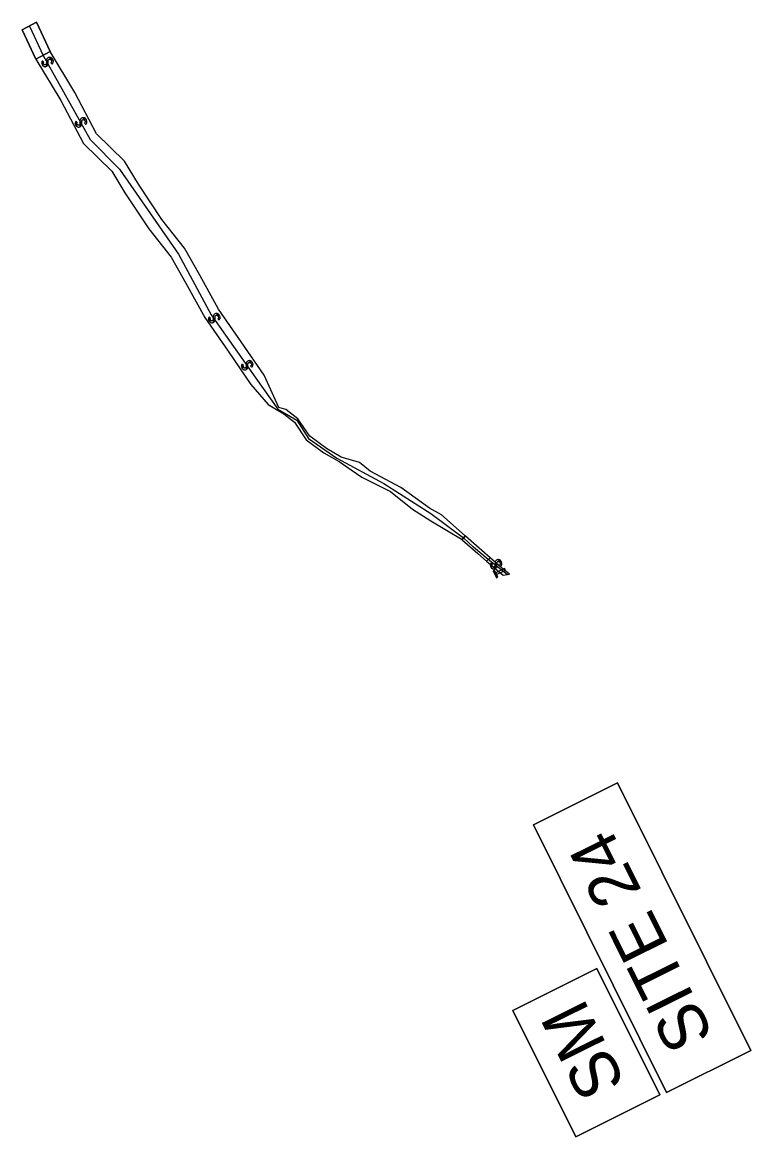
# Model space of a CAD drawing. Extents: x 474218 to 481634, y 484357 to 504997.
# Drawn here: x 475815 to 476040.6, y 502013 to 502358.5 of the extents above; entities that cross this region are included whole.
import ezdxf

# ---------------------------------------------------------------- set-up
doc = ezdxf.new("R2010")
doc.units = 0
for name, color, linetype in [('Exist Hydro Jurisdictional Stream or Body of Water', 7, 'Continuous'), ('Old_Level_29', 7, 'Continuous'), ('Prop Earthen Structure Impacts In Surface Waters Hatching CELL', 7, 'Continuous'), ('Prop Grid Mask', 7, 'Continuous'), ('Scratch_Level_4', 7, 'Continuous'), ('Temp Earthen Structure Impacts In Surface Waters Hatching CELL', 7, 'Continuous')]:
    doc.layers.add(name, color=color, linetype=linetype)

msp = doc.modelspace()

# ---------------------------------------------------------------- linework, layer by layer
at = {"layer": 'Exist Hydro Jurisdictional Stream or Body of Water'}
msp.add_lwpolyline([(475986.41, 502012.99), (475966.94, 502052.14), (475992.98, 502065.09), (476012.45, 502025.94)], close=True, dxfattribs=at)
at = {"layer": 'Old_Level_29'}
msp.add_lwpolyline([(476014.56, 502026.73), (475973.3, 502109.69), (475999.35, 502122.65), (476040.6, 502039.68)], close=True, dxfattribs=at)
at = {"layer": 'Prop Earthen Structure Impacts In Surface Waters Hatching CELL'}
for p, q in [((475823.61, 502349.4), (475819.19, 502347.05)), ((475891.15, 502240.01), (475895.93, 502237.08)), ((475896.62, 502238.44), (475894.44, 502239.07)), ((475951.2, 502198.09), (475952.13, 502199.28)), ((475952.13, 502199.28), (475951.2, 502198.09)), ((475951.2, 502198.09), (475951.2, 502198.09)), ((475952.13, 502199.28), (475952.13, 502199.28)), ((475952.26, 502199.17), (475952.13, 502199.28)), ((475959.85, 502192.46), (475952.26, 502199.17)), ((475956.05, 502193.82), (475958.78, 502191.4)), ((475958.78, 502191.4), (475959.85, 502192.46))]:
    msp.add_line(p, q, dxfattribs=at)
for points in [[(475819.19, 502347.05), (475826.88, 502334.26), (475833.91, 502320.91), (475842.67, 502312.33), (475846.73, 502305.58), (475854.13, 502294.43), (475861.06, 502285.62), (475865.62, 502277.59), (475871.47, 502266.94), (475878.68, 502256.55), (475885.74, 502246.18), (475891.15, 502240.01)], [(475894.44, 502239.07), (475889.84, 502249.04), (475882.8, 502259.38), (475875.72, 502269.57), (475869.98, 502280.03), (475865.22, 502288.42), (475858.18, 502297.36), (475850.96, 502308.25), (475846.63, 502315.45), (475837.97, 502323.93), (475831.23, 502336.71), (475823.61, 502349.4)], [(475895.93, 502237.08), (475899.24, 502234.54), (475902.93, 502229.07), (475908.34, 502225.05), (475913.12, 502222.31), (475916.83, 502219.68), (475920.17, 502217.49), (475929, 502213.03), (475935.81, 502207.51), (475941.49, 502203.88), (475951.2, 502198.09), (475951.2, 502198.09)], [(475952.13, 502199.28), (475944.77, 502205.78), (475941.1, 502207.85), (475932.26, 502214.25), (475922.72, 502219.3), (475919.39, 502221.97), (475913.72, 502223.69), (475909.16, 502226.3), (475904.03, 502230.12), (475900.34, 502235.58), (475896.62, 502238.44)], [(475951.2, 502198.09), (475951.26, 502198.05), (475956.05, 502193.82)]]:
    msp.add_lwpolyline(points, dxfattribs=at)
for points in [[(475822.54, 502344.87), (475822.65, 502344.94), (475822.35, 502345.53), (475822.27, 502345.41), (475822.1, 502345.31), (475822.09, 502345.3), (475822.04, 502345.3), (475821.91, 502345.28), (475821.84, 502345.31), (475821.76, 502345.35), (475821.72, 502345.36), (475821.7, 502345.38), (475821.64, 502345.45), (475821.57, 502345.54), (475821.13, 502346.41), (475821.09, 502346.36), (475821.01, 502346.14), (475820.99, 502346.09), (475820.98, 502345.76), (475821.37, 502344.97), (475821.62, 502344.81), (475821.69, 502344.77), (475821.9, 502344.73), (475821.98, 502344.71), (475822.01, 502344.71), (475822.04, 502344.7), (475822.05, 502344.7), (475822.08, 502344.71), (475822.14, 502344.72), (475822.18, 502344.73), (475822.31, 502344.76), (475822.36, 502344.77), (475822.37, 502344.77)], [(475821.53, 502346.05), (475821.6, 502346.19), (475821.37, 502346.36), (475821.3, 502346.41), (475821.19, 502346.49), (475821.17, 502346.47), (475821.17, 502346.46), (475821.15, 502346.44), (475821.13, 502346.41), (475821.57, 502345.54), (475821.48, 502345.78), (475821.49, 502345.82), (475821.49, 502345.83), (475821.49, 502345.88), (475821.5, 502346)], [(475823.83, 502346.89), (475823.96, 502346.71), (475823.52, 502347.59), (475823.48, 502347.6), (475823.47, 502347.6), (475823.46, 502347.6), (475823.38, 502347.61), (475823.35, 502347.6), (475823.33, 502347.6), (475823.23, 502347.57), (475823.19, 502347.56), (475823.15, 502347.55), (475823.02, 502347.52), (475822.95, 502347.47), (475822.78, 502347.36), (475822.71, 502347.32), (475822.66, 502347.25), (475822.58, 502347.12), (475822.58, 502347.12), (475822.51, 502347.02), (475822.49, 502346.91), (475822.43, 502346.64), (475822.43, 502346.56), (475822.42, 502346.21), (475822.43, 502346.03), (475822.85, 502345.19), (475822.88, 502345.28), (475822.95, 502345.5), (475822.96, 502345.58), (475822.98, 502345.91), (475822.98, 502346.07), (475822.98, 502346.31), (475822.99, 502346.6), (475823.02, 502346.69), (475823.06, 502346.81), (475823.21, 502346.95), (475823.28, 502346.98), (475823.41, 502347.03), (475823.45, 502347.03), (475823.5, 502347.03), (475823.62, 502347.03), (475823.65, 502347.01), (475823.69, 502346.98), (475823.81, 502346.91), (475823.82, 502346.91)], [(475824.59, 502346.46), (475824.44, 502346.92), (475824.15, 502347.34), (475824.15, 502347.34), (475823.8, 502347.54), (475823.76, 502347.57), (475823.52, 502347.59), (475823.96, 502346.71), (475824.04, 502346.46), (475824.04, 502346.45), (475824.04, 502346.44), (475824.04, 502346.28), (475824.04, 502346.22), (475824.03, 502346.2), (475823.97, 502346.08), (475823.95, 502346.02), (475823.92, 502346), (475823.83, 502345.89), (475824.07, 502345.7), (475824.14, 502345.64), (475824.22, 502345.58), (475824.3, 502345.65), (475824.31, 502345.67), (475824.33, 502345.69), (475824.39, 502345.74), (475824.39, 502345.75), (475824.39, 502345.75), (475824.42, 502345.8), (475824.53, 502346.01), (475824.55, 502346.04), (475824.59, 502346.45)], [(475821.35, 502345.01), (475821.37, 502344.97), (475820.98, 502345.76), (475820.98, 502345.74), (475821.12, 502345.33), (475821.12, 502345.33)], [(475822.79, 502345.12), (475822.85, 502345.19), (475822.43, 502346.03), (475822.44, 502345.84), (475822.39, 502345.59), (475822.35, 502345.53), (475822.65, 502344.94), (475822.69, 502344.99)], [(475834.21, 502328.16), (475834.34, 502327.98), (475833.91, 502328.86), (475833.86, 502328.87), (475833.86, 502328.87), (475833.85, 502328.87), (475833.76, 502328.88), (475833.74, 502328.87), (475833.72, 502328.87), (475833.61, 502328.84), (475833.57, 502328.83), (475833.53, 502328.82), (475833.4, 502328.79), (475833.33, 502328.74), (475833.16, 502328.63), (475833.09, 502328.59), (475833.05, 502328.52), (475832.96, 502328.39), (475832.96, 502328.39), (475832.89, 502328.29), (475832.87, 502328.18), (475832.81, 502327.91), (475832.81, 502327.83), (475832.81, 502327.48), (475832.81, 502327.3), (475833.23, 502326.46), (475833.26, 502326.55), (475833.34, 502326.77), (475833.34, 502326.85), (475833.37, 502327.18), (475833.37, 502327.34), (475833.37, 502327.58), (475833.37, 502327.87), (475833.4, 502327.96), (475833.44, 502328.08), (475833.59, 502328.22), (475833.67, 502328.25), (475833.79, 502328.3), (475833.83, 502328.3), (475833.88, 502328.3), (475834, 502328.3), (475834.03, 502328.28), (475834.08, 502328.25), (475834.19, 502328.18), (475834.2, 502328.18)], [(475834.97, 502327.73), (475834.82, 502328.19), (475834.53, 502328.61), (475834.53, 502328.61), (475834.19, 502328.81), (475834.14, 502328.84), (475833.91, 502328.86), (475834.34, 502327.98), (475834.43, 502327.73), (475834.43, 502327.73), (475834.43, 502327.71), (475834.42, 502327.55), (475834.42, 502327.49), (475834.41, 502327.47), (475834.36, 502327.35), (475834.33, 502327.29), (475834.31, 502327.27), (475834.21, 502327.16), (475834.46, 502326.97), (475834.52, 502326.91), (475834.6, 502326.85), (475834.68, 502326.92), (475834.7, 502326.94), (475834.72, 502326.96), (475834.77, 502327.01), (475834.78, 502327.02), (475834.78, 502327.02), (475834.8, 502327.07), (475834.92, 502327.28), (475834.93, 502327.31), (475834.97, 502327.72)], [(475832.92, 502326.14), (475833.03, 502326.21), (475832.74, 502326.8), (475832.66, 502326.68), (475832.49, 502326.58), (475832.48, 502326.57), (475832.43, 502326.57), (475832.29, 502326.55), (475832.23, 502326.58), (475832.14, 502326.62), (475832.11, 502326.63), (475832.09, 502326.65), (475832.03, 502326.72), (475831.95, 502326.81), (475831.52, 502327.68), (475831.48, 502327.63), (475831.39, 502327.41), (475831.37, 502327.36), (475831.37, 502327.03), (475831.75, 502326.24), (475832.01, 502326.08), (475832.07, 502326.04), (475832.29, 502326), (475832.36, 502325.98), (475832.4, 502325.98), (475832.43, 502325.97), (475832.43, 502325.97), (475832.46, 502325.98), (475832.52, 502325.99), (475832.56, 502326), (475832.69, 502326.03), (475832.74, 502326.04), (475832.75, 502326.04)], [(475831.73, 502326.28), (475831.75, 502326.24), (475831.37, 502327.03), (475831.37, 502327.01), (475831.51, 502326.6), (475831.51, 502326.6)], [(475831.91, 502327.32), (475831.98, 502327.46), (475831.76, 502327.63), (475831.68, 502327.68), (475831.58, 502327.76), (475831.56, 502327.74), (475831.55, 502327.73), (475831.54, 502327.71), (475831.52, 502327.68), (475831.95, 502326.81), (475831.87, 502327.05), (475831.87, 502327.09), (475831.87, 502327.1), (475831.88, 502327.15), (475831.89, 502327.27)], [(475833.18, 502326.39), (475833.23, 502326.46), (475832.81, 502327.3), (475832.82, 502327.11), (475832.77, 502326.86), (475832.74, 502326.8), (475833.03, 502326.21), (475833.07, 502326.26)], [(475874.21, 502265.47), (475874.33, 502265.54), (475874.03, 502266.13), (475873.95, 502266), (475873.78, 502265.91), (475873.77, 502265.9), (475873.72, 502265.89), (475873.58, 502265.88), (475873.52, 502265.91), (475873.44, 502265.94), (475873.4, 502265.96), (475873.38, 502265.98), (475873.32, 502266.05), (475873.24, 502266.14), (475872.81, 502267.01), (475872.77, 502266.96), (475872.68, 502266.74), (475872.66, 502266.69), (475872.66, 502266.35), (475873.05, 502265.57), (475873.3, 502265.41), (475873.37, 502265.36), (475873.58, 502265.33), (475873.66, 502265.31), (475873.69, 502265.31), (475873.72, 502265.3), (475873.73, 502265.3), (475873.75, 502265.31), (475873.81, 502265.32), (475873.86, 502265.33), (475873.99, 502265.36), (475874.03, 502265.37), (475874.05, 502265.37)], [(475873.2, 502266.64), (475873.27, 502266.79), (475873.05, 502266.96), (475872.97, 502267.01), (475872.87, 502267.09), (475872.85, 502267.06), (475872.85, 502267.06), (475872.83, 502267.04), (475872.81, 502267.01), (475873.24, 502266.14), (475873.16, 502266.37), (475873.16, 502266.42), (475873.17, 502266.43), (475873.17, 502266.48), (475873.18, 502266.59)], [(475874.47, 502265.72), (475874.52, 502265.78), (475874.11, 502266.63), (475874.11, 502266.44), (475874.07, 502266.19), (475874.03, 502266.13), (475874.33, 502265.53), (475874.37, 502265.59)], [(475875.5, 502267.49), (475875.64, 502267.31), (475875.2, 502268.19), (475875.15, 502268.2), (475875.15, 502268.2), (475875.14, 502268.2), (475875.06, 502268.21), (475875.03, 502268.2), (475875.01, 502268.2), (475874.91, 502268.17), (475874.86, 502268.16), (475874.83, 502268.15), (475874.7, 502268.11), (475874.63, 502268.07), (475874.46, 502267.96), (475874.38, 502267.92), (475874.34, 502267.85), (475874.25, 502267.72), (475874.25, 502267.72), (475874.19, 502267.62), (475874.16, 502267.51), (475874.11, 502267.24), (475874.1, 502267.16), (475874.1, 502266.81), (475874.11, 502266.63), (475874.52, 502265.78), (475874.56, 502265.88), (475874.63, 502266.1), (475874.64, 502266.17), (475874.66, 502266.51), (475874.66, 502266.67), (475874.66, 502266.91), (475874.66, 502267.2), (475874.69, 502267.29), (475874.73, 502267.41), (475874.88, 502267.55), (475874.96, 502267.58), (475875.09, 502267.63), (475875.13, 502267.63), (475875.18, 502267.63), (475875.29, 502267.62), (475875.33, 502267.6), (475875.37, 502267.58), (475875.48, 502267.51), (475875.5, 502267.5)], [(475876.26, 502267.06), (475876.12, 502267.52), (475875.83, 502267.93), (475875.82, 502267.94), (475875.48, 502268.14), (475875.44, 502268.16), (475875.2, 502268.19), (475875.64, 502267.31), (475875.72, 502267.06), (475875.72, 502267.05), (475875.72, 502267.03), (475875.72, 502266.88), (475875.72, 502266.82), (475875.7, 502266.8), (475875.65, 502266.67), (475875.63, 502266.62), (475875.6, 502266.59), (475875.51, 502266.49), (475875.75, 502266.29), (475875.82, 502266.24), (475875.9, 502266.18), (475875.98, 502266.25), (475875.99, 502266.27), (475876.01, 502266.29), (475876.06, 502266.34), (475876.07, 502266.35), (475876.07, 502266.35), (475876.09, 502266.39), (475876.21, 502266.61), (475876.22, 502266.64), (475876.26, 502267.05)], [(475873.02, 502265.61), (475873.05, 502265.57), (475872.66, 502266.35), (475872.66, 502266.34), (475872.8, 502265.92), (475872.8, 502265.92)], [(475885.7, 502252.89), (475885.83, 502252.71), (475885.39, 502253.59), (475885.35, 502253.6), (475885.34, 502253.6), (475885.33, 502253.6), (475885.25, 502253.61), (475885.22, 502253.6), (475885.2, 502253.59), (475885.1, 502253.57), (475885.06, 502253.56), (475885.02, 502253.55), (475884.89, 502253.51), (475884.82, 502253.47), (475884.65, 502253.36), (475884.58, 502253.31), (475884.53, 502253.25), (475884.45, 502253.12), (475884.45, 502253.12), (475884.38, 502253.02), (475884.36, 502252.91), (475884.3, 502252.64), (475884.3, 502252.56), (475884.29, 502252.2), (475884.3, 502252.02), (475884.72, 502251.18), (475884.75, 502251.28), (475884.82, 502251.5), (475884.83, 502251.57), (475884.85, 502251.91), (475884.85, 502252.06), (475884.85, 502252.31), (475884.86, 502252.6), (475884.89, 502252.69), (475884.93, 502252.8), (475885.08, 502252.95), (475885.15, 502252.98), (475885.28, 502253.03), (475885.32, 502253.02), (475885.37, 502253.02), (475885.49, 502253.02), (475885.52, 502253), (475885.56, 502252.98), (475885.68, 502252.91), (475885.69, 502252.9)], [(475886.46, 502252.45), (475886.31, 502252.92), (475886.02, 502253.33), (475886.02, 502253.33), (475885.67, 502253.54), (475885.63, 502253.56), (475885.39, 502253.59), (475885.83, 502252.71), (475885.91, 502252.46), (475885.91, 502252.45), (475885.91, 502252.43), (475885.91, 502252.28), (475885.91, 502252.22), (475885.9, 502252.19), (475885.84, 502252.07), (475885.82, 502252.02), (475885.79, 502251.99), (475885.7, 502251.89), (475885.94, 502251.69), (475886.01, 502251.64), (475886.09, 502251.57), (475886.17, 502251.65), (475886.18, 502251.67), (475886.21, 502251.69), (475886.26, 502251.74), (475886.26, 502251.75), (475886.26, 502251.75), (475886.29, 502251.79), (475886.4, 502252.01), (475886.42, 502252.04), (475886.46, 502252.45)], [(475884.41, 502250.87), (475884.52, 502250.93), (475884.22, 502251.53), (475884.14, 502251.4), (475883.97, 502251.3), (475883.96, 502251.3), (475883.91, 502251.29), (475883.78, 502251.28), (475883.72, 502251.31), (475883.63, 502251.34), (475883.59, 502251.36), (475883.57, 502251.38), (475883.51, 502251.45), (475883.44, 502251.54), (475883, 502252.41), (475882.96, 502252.36), (475882.88, 502252.14), (475882.86, 502252.09), (475882.85, 502251.75), (475883.24, 502250.97), (475883.49, 502250.81), (475883.56, 502250.76), (475883.77, 502250.72), (475883.85, 502250.71), (475883.89, 502250.7), (475883.91, 502250.7), (475883.92, 502250.7), (475883.95, 502250.71), (475884.01, 502250.72), (475884.05, 502250.73), (475884.18, 502250.75), (475884.23, 502250.76), (475884.24, 502250.77)], [(475883.22, 502251.01), (475883.24, 502250.97), (475882.85, 502251.75), (475882.85, 502251.74), (475882.99, 502251.32), (475882.99, 502251.32)], [(475883.4, 502252.04), (475883.47, 502252.19), (475883.24, 502252.35), (475883.17, 502252.41), (475883.06, 502252.49), (475883.04, 502252.46), (475883.04, 502252.46), (475883.02, 502252.44), (475883, 502252.41), (475883.44, 502251.54), (475883.35, 502251.77), (475883.36, 502251.82), (475883.36, 502251.83), (475883.36, 502251.88), (475883.37, 502251.99)], [(475884.67, 502251.12), (475884.72, 502251.18), (475884.3, 502252.02), (475884.31, 502251.84), (475884.26, 502251.59), (475884.22, 502251.53), (475884.52, 502250.93), (475884.56, 502250.98)]]:
    msp.add_lwpolyline(points, close=True, dxfattribs=at)
at = {"layer": 'Prop Grid Mask'}
for points in [[(476040.6, 502039.68), (475999.35, 502122.65), (475973.3, 502109.69), (476014.56, 502026.73)], [(476012.45, 502025.94), (475992.98, 502065.09), (475966.94, 502052.14), (475986.41, 502012.99)]]:
    msp.add_lwpolyline(points, close=True, dxfattribs=at)
at = {"layer": 'Scratch_Level_4'}
msp.add_line((475965.14, 502187.26), (475959.3, 502191.95), dxfattribs=at)
msp.add_lwpolyline([(475819.19, 502347.05), (475814.96, 502356.13), (475819.38, 502358.48), (475823.61, 502349.4)], close=True, dxfattribs=at)
for points in [[(475817.17, 502357.3), (475821.4, 502348.22)], [(475821.4, 502348.22), (475836.03, 502322.16), (475845.1, 502312.95), (475863.38, 502286.63), (475873.46, 502267.79), (475887.3, 502248.2), (475894.1, 502238.57), (475899.97, 502235.09), (475903.6, 502229.49), (475912.39, 502223.39), (475926.97, 502215.49), (475941.55, 502206.24), (475951.6, 502198.6)], [(475959.3, 502191.95), (475954.77, 502195.8), (475951.6, 502198.6)]]:
    msp.add_lwpolyline(points, dxfattribs=at)
at = {"layer": 'Temp Earthen Structure Impacts In Surface Waters Hatching CELL'}
msp.add_line((475819.19, 502347.05), (475823.61, 502349.4), dxfattribs=at)
for points in [[(475823.61, 502349.4), (475819.38, 502358.48), (475814.96, 502356.13), (475819.19, 502347.05)], [(475965.86, 502187.41), (475963.32, 502189.5), (475959.85, 502192.46), (475958.78, 502191.4), (475960.69, 502189.72), (475963.96, 502187.03), (475965.86, 502187.41)]]:
    msp.add_lwpolyline(points, dxfattribs=at)
for points in [[(475961.51, 502189.18), (475961.62, 502189.25), (475961.33, 502189.84), (475961.25, 502189.72), (475961.08, 502189.62), (475961.07, 502189.61), (475961.02, 502189.61), (475960.88, 502189.59), (475960.82, 502189.62), (475960.73, 502189.66), (475960.7, 502189.67), (475960.68, 502189.69), (475960.62, 502189.76), (475960.54, 502189.85), (475960.11, 502190.72), (475960.07, 502190.67), (475959.98, 502190.45), (475959.96, 502190.4), (475959.96, 502190.07), (475960.34, 502189.28), (475960.6, 502189.12), (475960.66, 502189.08), (475960.88, 502189.04), (475960.95, 502189.02), (475960.99, 502189.02), (475961.02, 502189.01), (475961.02, 502189.01), (475961.05, 502189.02), (475961.11, 502189.03), (475961.15, 502189.04), (475961.28, 502189.07), (475961.33, 502189.08), (475961.34, 502189.08)], [(475960.5, 502190.36), (475960.57, 502190.5), (475960.35, 502190.67), (475960.27, 502190.72), (475960.17, 502190.8), (475960.15, 502190.78), (475960.14, 502190.77), (475960.13, 502190.75), (475960.11, 502190.72), (475960.54, 502189.85), (475960.46, 502190.09), (475960.46, 502190.13), (475960.46, 502190.14), (475960.47, 502190.19), (475960.48, 502190.31)], [(475962.8, 502191.2), (475962.93, 502191.02), (475962.5, 502191.9), (475962.45, 502191.91), (475962.45, 502191.91), (475962.44, 502191.91), (475962.35, 502191.92), (475962.33, 502191.91), (475962.31, 502191.91), (475962.2, 502191.88), (475962.16, 502191.87), (475962.12, 502191.86), (475961.99, 502191.83), (475961.92, 502191.78), (475961.75, 502191.67), (475961.68, 502191.63), (475961.64, 502191.56), (475961.55, 502191.43), (475961.55, 502191.43), (475961.48, 502191.33), (475961.46, 502191.22), (475961.4, 502190.95), (475961.4, 502190.87), (475961.4, 502190.52), (475961.4, 502190.34), (475961.82, 502189.5), (475961.85, 502189.59), (475961.93, 502189.81), (475961.93, 502189.89), (475961.96, 502190.22), (475961.96, 502190.38), (475961.96, 502190.62), (475961.96, 502190.91), (475961.99, 502191), (475962.03, 502191.12), (475962.18, 502191.26), (475962.26, 502191.29), (475962.38, 502191.34), (475962.42, 502191.34), (475962.47, 502191.34), (475962.59, 502191.34), (475962.62, 502191.32), (475962.67, 502191.29), (475962.78, 502191.22), (475962.79, 502191.22)], [(475963.56, 502190.77), (475963.41, 502191.23), (475963.12, 502191.65), (475963.12, 502191.65), (475962.78, 502191.85), (475962.73, 502191.88), (475962.5, 502191.9), (475962.93, 502191.02), (475963.02, 502190.77), (475963.02, 502190.77), (475963.02, 502190.75), (475963.01, 502190.59), (475963.01, 502190.53), (475963, 502190.51), (475962.95, 502190.39), (475962.92, 502190.33), (475962.9, 502190.31), (475962.8, 502190.2), (475963.05, 502190.01), (475963.11, 502189.95), (475963.19, 502189.89), (475963.27, 502189.96), (475963.29, 502189.98), (475963.31, 502190), (475963.36, 502190.05), (475963.37, 502190.06), (475963.37, 502190.06), (475963.39, 502190.11), (475963.51, 502190.32), (475963.52, 502190.35), (475963.56, 502190.76)], [(475960.32, 502189.32), (475960.34, 502189.28), (475959.96, 502190.07), (475959.96, 502190.05), (475960.1, 502189.64), (475960.1, 502189.64)], [(475961.87, 502186.25), (475962.31, 502186.47), (475961.22, 502188.64), (475960.79, 502188.43)], [(475961.77, 502189.43), (475961.82, 502189.5), (475961.4, 502190.34), (475961.41, 502190.15), (475961.36, 502189.9), (475961.33, 502189.84), (475961.62, 502189.25), (475961.66, 502189.3)], [(475961.89, 502187.3), (475964.6, 502188.65), (475964.34, 502189.16), (475961.64, 502187.81)]]:
    msp.add_lwpolyline(points, close=True, dxfattribs=at)

# ---------------------------------------------------------------- texts
at = {"layer": 'Exist Hydro Jurisdictional Stream or Body of Water'}
msp.add_text('SM', height=15, rotation=116.4411, dxfattribs=at).set_placement((476002.01, 502029.46))
at = {"layer": 'Old_Level_29'}
msp.add_text('SITE 24', height=15, rotation=116.4411, dxfattribs=at).set_placement((476029.34, 502044.17))

doc.saveas('drawing.dxf')
